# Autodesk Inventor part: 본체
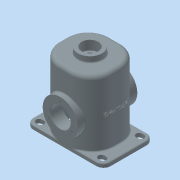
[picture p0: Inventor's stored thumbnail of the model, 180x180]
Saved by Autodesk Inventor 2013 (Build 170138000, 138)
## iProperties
Company: 한국ATC센터
Created: 2014-10
Part Number: 본체
Document SubType Name: Modeling
Designer: 한국ATC센터
Density: 2.71 g/cm^3
Material: 알루미늄 6061
Mass: 2951.25 g
Surface Area: 2149.43 cm^2
Volume: 1089.02 cm^3
Author: KYOUNG IL JANG
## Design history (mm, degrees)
sketch "스케치1"
  geometry: L1 (-70, 65)-(70, 65); L2 (70, 65)-(70, -65); L3 (70, -65)-(-70, -65); L4 (-70, -65)-(-70, 65); 3 further points
  constraints: 8 end point, 2 midpoint, 2 parallel, 1 horizontal, 1 horizontal alignment, 1 perpendicular, 1 vertical alignment
  dimensions: "d0" = 140 distance of L2.end L3.end; "d68" = 130 distance of L3.end L1.start
extrude "돌출1" new body sketch "스케치1" distance "d1" = 180; taper "d2" = 0 deg
fillet "모깎기1" dims "d3" = 55
feature "쉘1" dims "d4" = 10
sketch "스케치2"
  geometry: L1 (-70, 10)-(-70, -10) reference; L2 (-15, -65)-(-82, -65); L3 (-82, 65)-(-15, 65); L4 (-83, 57)-(-78, 57); L5 (-78, 41)-(-83, 41); L6 (-100, 47)-(-100, -47); A1 r 55 centre (-15, 10) between (-15, 65) and (-70, 10) reference; A2 r 55 centre (-15, -10) between (-70, -10) and (-15, -65) reference; A3 r 8 centre (-78, 49) between (-78, 41) and (-78, 57); A4 r 8 centre (-83, 49) between (-83, 57) and (-83, 41); A5 r 18 centre (-82, 47) between (-82, 65) and (-100, 47); A6 r 18 centre (-82, -47) between (-100, -47) and (-82, -65); 1 further point
  constraints: 10 end point, 9 tangent, 8 point on circle, 4 centre point, 2 parallel, 2 perpendicular, 1 equal radius
  dimensions: "d6" = 49 vertical distance of point (0, 0) A3.centre; "d8" = 16 distance between parallel lines of L4 L5; "d64" = 18 radius of A5; "d65" = 8 distance from line of A3.centre L1; "d66" = 30 distance between parallel lines of L6 L1; "d67" = 5 distance of A4.centre A3.centre
extrude "돌출2" join sketch "스케치2" distance "d9" = 10; taper "d10" = 0 deg
extrude "돌출3" cut sketch "스케치2" stored distance "d11" = 10; taper "d12" = 0 deg
sketch "스케치3"
  geometry: L1 (-65, 10)-(-65, 180) reference; L2 (-55, 0)-(-55, 170) reference; L3 (-77, 75)-(-45, 75); L4 (10, 0)-(-10, 0) reference; L5 (-77, 75)-(-77, 120.5); L6 (-77, 120.5)-(-55, 120.5); L7 (-55, 120.5)-(-45, 110.5); L8 (-45, 110.5)-(-45, 75); 3 further points
  constraints: 10 end point, 4 perpendicular, 1 point on line
  dimensions: "d13" = 75 distance between parallel lines of L3 L4; "d14" = 12 distance from line of L1 L3.start; "d15" = 10 distance from line of L3.end L2; "d16" = 91 diameter of L6 L3; "d17" = 135 deg angle of L7 L2
revolve "회전1" sketch "스케치3" stored, may be unused: angle "d18" = 90 deg
sketch "스케치4"
  geometry: C1 r 45.5 at (0, 0) reference; 2 further points
  constraints: 1 vertical alignment
  dimensions: "d19" = 35 distance of C1.centre point (0, 35)
hole "구멍1" sketch "스케치4" at (0, 35) diameter "d20" = 3.459; stored, may be unused: countersink angle "d24" = 90 deg, drill point angle "d26" = 118 deg; dims "d21" = 13, "d22" = 4, "d23" = 2, "d25" = 16
fillet "모깎기2" dims "d30" = 3
hole "구멍2" diameter "d33" = 52; stored, may be unused: countersink angle "d37" = 90 deg, drill point angle "d39" = 118 deg; dims "d31" = 10, "d32" = 10, "d34" = 13, "d35" = 4, "d36" = 2, "d38" = 16
sketch "스케치5"
  geometry: C1 r 31 at (0, 0); 1 further point
  constraints: 1 centre point, 1 coincident
  dimensions: "d40" = 62 diameter of C1
extrude "돌출4" join sketch "스케치5" distance "d41" = 15; taper "d42" = 0 deg
hole "구멍3" diameter "d45" = 43; stored, may be unused: countersink angle "d49" = 90 deg, drill point angle "d51" = 118 deg; dims "d43" = 10, "d44" = 10, "d46" = 13, "d47" = 4, "d48" = 2, "d50" = 16
fillet "모깎기3" dims "d52" = 3
fillet "모깎기4" dims "d53" = 3
chamfer "모따기1" distance "d55" = 1; stored, may be unused: second distance "d56" = 2, angle "d57" = 45 deg
sketch "스케치6"
  geometry: 2 further points
  constraints: 1 vertical alignment, 1 other
  dimensions: "d71" = 90 distance of point (0, 0) point (0, 90)
feature "엠보싱2" sketch "스케치6" dims "d0" = 140, "d68" = 130, "d72" = 1, "d73" = 0
fillet "모깎기6" dims "d74" = 10
sketch "스케치7"
  geometry: C1 r 15 at (0, 0); C2 r 21.5 at (0, 0) reference; C3 r 25 at (0, 0); 1 further point
  constraints: 2 centre point, 2 coincident
  dimensions: "d61" = 30 diameter of C1; "d75" = 50 diameter of C3
extrude "돌출5" join sketch "스케치7" distance "d62" = 10; taper "d63" = 0 deg
feature "면 이동1" dims "d76" = 1
node "솔리드1"
mirror "대칭1"
mirror "대칭2"
pattern_circular "원형 패턴1" dims angle "d28" = 360 deg
mirror "대칭3"
